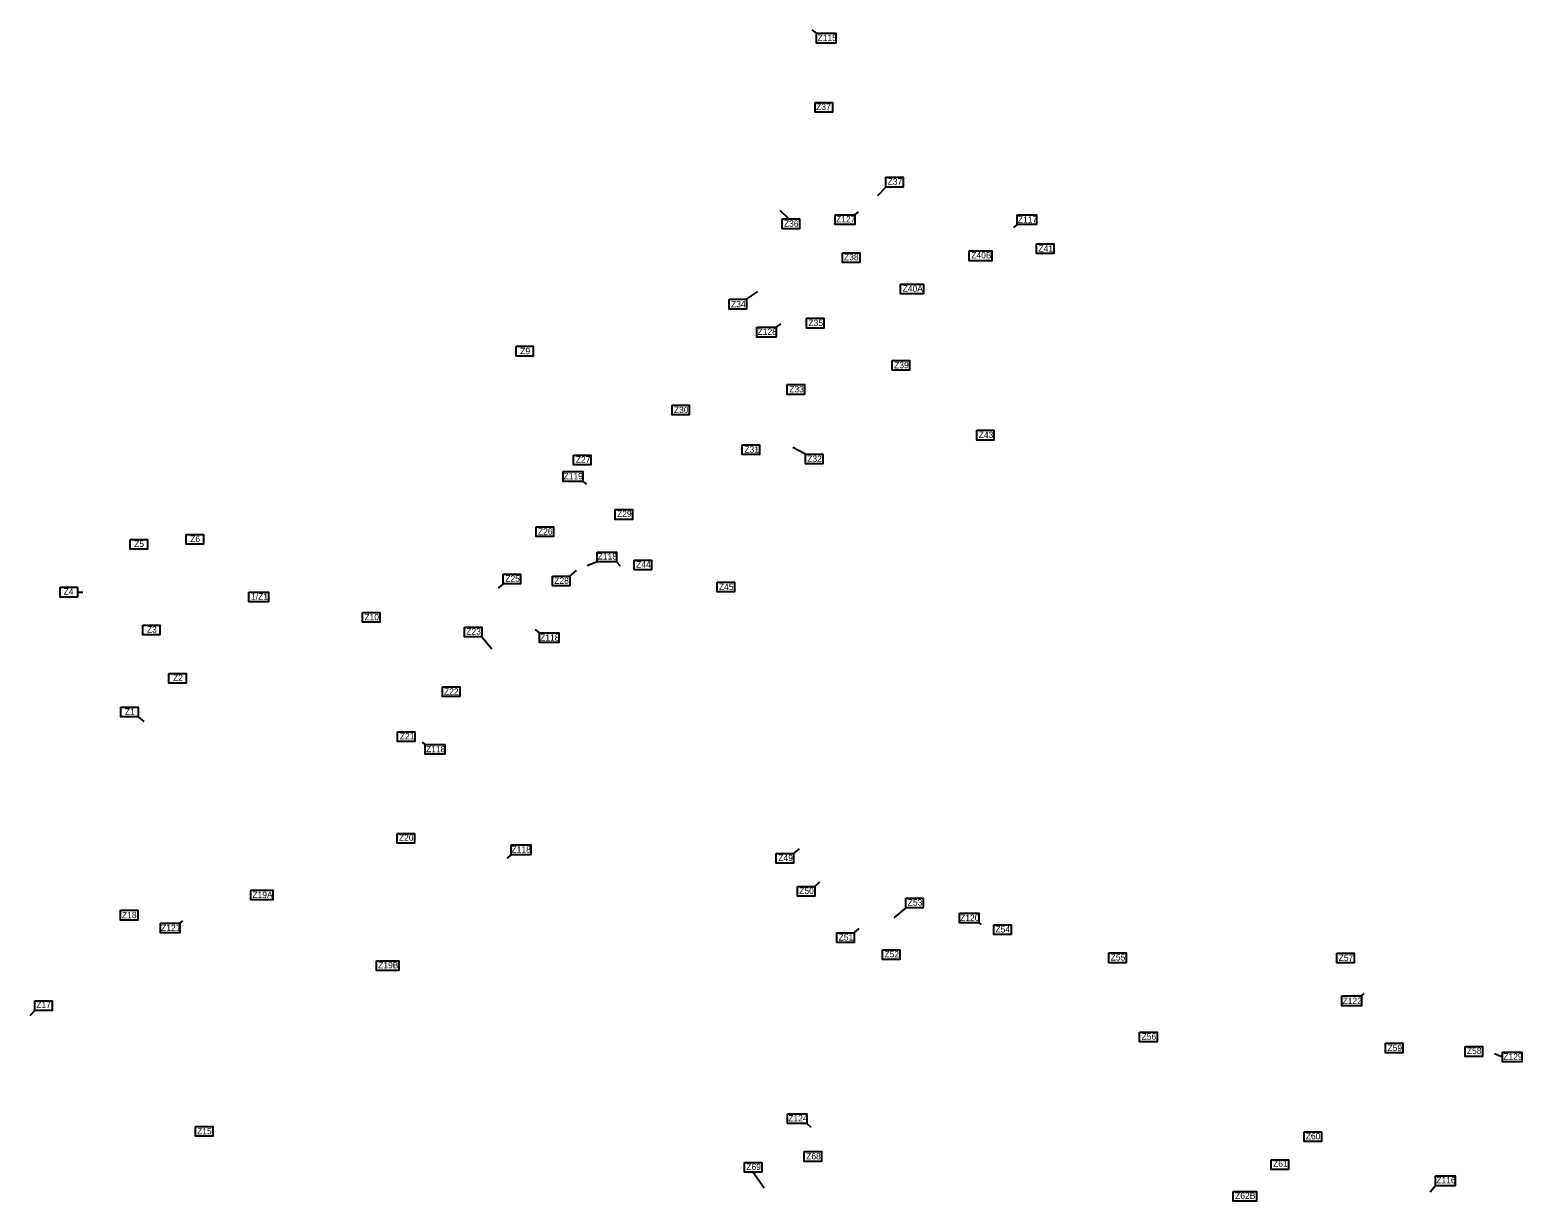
# Model space of a CAD drawing. Extents: x -443483 to -437761, y -1135258 to -1129797.
# Drawn here: x -443022 to -440666, y -1131646 to -1129797 of the extents above; entities that cross this region are included whole.
import ezdxf

# ---------------------------------------------------------------- set-up
doc = ezdxf.new("R2010")
doc.units = 0
doc.layers.add('Vrstva 3', color=7, linetype='Continuous')
doc.layers.add('Vrstva 8', color=7, linetype='Continuous')

msp = doc.modelspace()

# ---------------------------------------------------------------- linework, layer by layer
at = {"layer": 'Vrstva 3'}
for p, q in [((-441780.6, -1129802.1), (-441787.2, -1129796.7)), ((-441671, -1130044.8), (-441684, -1130058.8)), ((-441824.2, -1130095.2), (-441838, -1130081.7)), ((-441797.8, -1130466.6), (-441817.9, -1130456)), ((-442169.8, -1130659.1), (-442159.4, -1130650.4)), ((-442275.3, -1130671.3), (-442283.1, -1130678.3)), ((-442947.3, -1130684.5), (-442938.5, -1130684.6)), ((-442308.8, -1130754.9), (-442293.2, -1130773.8)), ((-442851.5, -1130881.4), (-442842.3, -1130888.4)), ((-441816.8, -1131096.9), (-441807.1, -1131089.6)), ((-441783.2, -1131148.9), (-441775.1, -1131141.9)), ((-441639.2, -1131182.7), (-441658.5, -1131198.7)), ((-441721, -1131222.3), (-441712.8, -1131215.4)), ((-443014.7, -1131344.8), (-443022.4, -1131353.5)), ((-441880.4, -1131600.1), (-441862.9, -1131625)), ((-440803, -1131621.5), (-440811.7, -1131631.9))]:
    msp.add_line(p, q, dxfattribs=at)
for points in [[(-441780.6, -1129802.1), (-441749.8, -1129802.1), (-441749.8, -1129817.5), (-441780.6, -1129817.5)], [(-441782.6, -1129911.3), (-441755.2, -1129911.3), (-441755.2, -1129926.7), (-441782.6, -1129926.7)], [(-441671, -1130029.4), (-441643.7, -1130029.4), (-441643.7, -1130044.8), (-441671, -1130044.8)], [(-441834.7, -1130095.2), (-441807.3, -1130095.2), (-441807.3, -1130110.6), (-441834.7, -1130110.6)], [(-441433.1, -1130134.4), (-441405.7, -1130134.4), (-441405.7, -1130149.8), (-441433.1, -1130149.8)], [(-441739.6, -1130148.5), (-441712.2, -1130148.5), (-441712.2, -1130163.9), (-441739.6, -1130163.9)], [(-441539.4, -1130145.7), (-441503.4, -1130145.7), (-441503.4, -1130161.1), (-441539.4, -1130161.1)], [(-441647.7, -1130198.3), (-441611.7, -1130198.3), (-441611.7, -1130213.7), (-441647.7, -1130213.7)], [(-441918.2, -1130222.1), (-441890.9, -1130222.1), (-441890.9, -1130237.5), (-441918.2, -1130237.5)], [(-441796.3, -1130252.1), (-441768.9, -1130252.1), (-441768.9, -1130267.5), (-441796.3, -1130267.5)], [(-442254.8, -1130296.3), (-442227.5, -1130296.3), (-442227.5, -1130311.7), (-442254.8, -1130311.7)], [(-441661.1, -1130318.6), (-441633.7, -1130318.6), (-441633.7, -1130334), (-441661.1, -1130334)], [(-441826.6, -1130356.8), (-441799.2, -1130356.8), (-441799.2, -1130372.2), (-441826.6, -1130372.2)], [(-442008.5, -1130389.3), (-441981.2, -1130389.3), (-441981.2, -1130404.7), (-442008.5, -1130404.7)], [(-441527.5, -1130428.9), (-441500.2, -1130428.9), (-441500.2, -1130444.3), (-441527.5, -1130444.3)], [(-441897.9, -1130451.8), (-441870.5, -1130451.8), (-441870.5, -1130467.2), (-441897.9, -1130467.2)], [(-442163.9, -1130468.1), (-442136.5, -1130468.1), (-442136.5, -1130483.5), (-442163.9, -1130483.5)], [(-441797.8, -1130466.6), (-441770.5, -1130466.6), (-441770.5, -1130482), (-441797.8, -1130482)], [(-442098.4, -1130554.1), (-442071.1, -1130554.1), (-442071.1, -1130569.5), (-442098.4, -1130569.5)], [(-442222.8, -1130581.2), (-442195.5, -1130581.2), (-442195.5, -1130596.5), (-442222.8, -1130596.5)], [(-442864.1, -1130601.3), (-442836.8, -1130601.3), (-442836.8, -1130616.7), (-442864.1, -1130616.7)], [(-442775.7, -1130593.4), (-442748.3, -1130593.4), (-442748.3, -1130608.8), (-442775.7, -1130608.8)], [(-442068.4, -1130633.9), (-442041.1, -1130633.9), (-442041.1, -1130649.3), (-442068.4, -1130649.3)], [(-442275.3, -1130655.9), (-442247.9, -1130655.9), (-442247.9, -1130671.3), (-442275.3, -1130671.3)], [(-442197.1, -1130659.1), (-442169.8, -1130659.1), (-442169.8, -1130674.5), (-442197.1, -1130674.5)], [(-441937.3, -1130668.5), (-441909.9, -1130668.5), (-441909.9, -1130683.9), (-441937.3, -1130683.9)], [(-442974.7, -1130676.8), (-442947.3, -1130676.8), (-442947.3, -1130692.2), (-442974.7, -1130692.2)], [(-442676.6, -1130684.2), (-442645.6, -1130684.2), (-442645.6, -1130699.6), (-442676.6, -1130699.6)], [(-442497.1, -1130716.5), (-442469.7, -1130716.5), (-442469.7, -1130731.9), (-442497.1, -1130731.9)], [(-442844.2, -1130736.3), (-442816.9, -1130736.3), (-442816.9, -1130751.7), (-442844.2, -1130751.7)], [(-442336.2, -1130739.6), (-442308.8, -1130739.6), (-442308.8, -1130754.9), (-442336.2, -1130754.9)], [(-442802.8, -1130812.7), (-442775.4, -1130812.7), (-442775.4, -1130828.1), (-442802.8, -1130828.1)], [(-442370.9, -1130833.9), (-442343.6, -1130833.9), (-442343.6, -1130849.2), (-442370.9, -1130849.2)], [(-442878.9, -1130866.1), (-442851.5, -1130866.1), (-442851.5, -1130881.4), (-442878.9, -1130881.4)], [(-442441.8, -1130904.7), (-442414.5, -1130904.7), (-442414.5, -1130920.1), (-442441.8, -1130920.1)], [(-442442.5, -1131065.5), (-442415.2, -1131065.5), (-442415.2, -1131080.9), (-442442.5, -1131080.9)], [(-441844.2, -1131096.9), (-441816.8, -1131096.9), (-441816.8, -1131112.3), (-441844.2, -1131112.3)], [(-442673.7, -1131154.7), (-442638.8, -1131154.7), (-442638.8, -1131170.1), (-442673.7, -1131170.1)], [(-441810.6, -1131148.9), (-441783.2, -1131148.9), (-441783.2, -1131164.3), (-441810.6, -1131164.3)], [(-441639.2, -1131167.3), (-441611.8, -1131167.3), (-441611.8, -1131182.7), (-441639.2, -1131182.7)], [(-442879.2, -1131186.7), (-442851.8, -1131186.7), (-442851.8, -1131202.1), (-442879.2, -1131202.1)], [(-441500.6, -1131209.7), (-441473.3, -1131209.7), (-441473.3, -1131225.1), (-441500.6, -1131225.1)], [(-441748.4, -1131222.3), (-441721, -1131222.3), (-441721, -1131237.7), (-441748.4, -1131237.7)], [(-441676, -1131249.1), (-441648.6, -1131249.1), (-441648.6, -1131264.5), (-441676, -1131264.5)], [(-441319, -1131254), (-441291.6, -1131254), (-441291.6, -1131269.4), (-441319, -1131269.4)], [(-440958.8, -1131254.3), (-440931.4, -1131254.3), (-440931.4, -1131269.7), (-440958.8, -1131269.7)], [(-442475.3, -1131266.3), (-442439.8, -1131266.3), (-442439.8, -1131281.7), (-442475.3, -1131281.7)], [(-443014.7, -1131329.4), (-442987.3, -1131329.4), (-442987.3, -1131344.8), (-443014.7, -1131344.8)], [(-441270.2, -1131379), (-441242.8, -1131379), (-441242.8, -1131394.4), (-441270.2, -1131394.4)], [(-440882, -1131396.5), (-440854.6, -1131396.5), (-440854.6, -1131411.9), (-440882, -1131411.9)], [(-440756.3, -1131401.9), (-440728.9, -1131401.9), (-440728.9, -1131417.3), (-440756.3, -1131417.3)], [(-442760.6, -1131528), (-442733.3, -1131528), (-442733.3, -1131543.4), (-442760.6, -1131543.4)], [(-441010.2, -1131536.4), (-440982.9, -1131536.4), (-440982.9, -1131551.8), (-441010.2, -1131551.8)], [(-441799.8, -1131567.7), (-441772.4, -1131567.7), (-441772.4, -1131583.1), (-441799.8, -1131583.1)], [(-441894.2, -1131584.7), (-441866.9, -1131584.7), (-441866.9, -1131600.1), (-441894.2, -1131600.1)], [(-441062.3, -1131580.5), (-441035, -1131580.5), (-441035, -1131595.9), (-441062.3, -1131595.9)], [(-440803, -1131606.1), (-440772.3, -1131606.1), (-440772.3, -1131621.5), (-440803, -1131621.5)], [(-441122.8, -1131630.5), (-441085.9, -1131630.5), (-441085.9, -1131645.9), (-441122.8, -1131645.9)]]:
    msp.add_lwpolyline(points, close=True, dxfattribs=at)
at = {"layer": 'Vrstva 8'}
for p, q in [((-441720.1, -1130088.6), (-441714.3, -1130084)), ((-441463.6, -1130104.2), (-441469.4, -1130108.5)), ((-441890.9, -1130222.1), (-441873, -1130210)), ((-441844, -1130266.2), (-441836.1, -1130260.9)), ((-442149.3, -1130509.6), (-442143.6, -1130514.2)), ((-442126.7, -1130636.5), (-442142.2, -1130643.1)), ((-442095.9, -1130636.5), (-442090.5, -1130642.7)), ((-442217.8, -1130748.4), (-442224.2, -1130743.6)), ((-442398, -1130924.7), (-442402.3, -1130921.1)), ((-442262.3, -1131099), (-442269.2, -1131104.3)), ((-442785.3, -1131206.9), (-442780.8, -1131203.4)), ((-441523.9, -1131206.4), (-441520.2, -1131209.2)), ((-440920.2, -1131322), (-440915.5, -1131317.9)), ((-440697.5, -1131418.4), (-440709.9, -1131413.3)), ((-441795.5, -1131523.2), (-441789.2, -1131529))]:
    msp.add_line(p, q, dxfattribs=at)
for points in [[(-441750.9, -1130088.6), (-441720.1, -1130088.6), (-441720.1, -1130104), (-441750.9, -1130104)], [(-441463.6, -1130088.8), (-441432.8, -1130088.8), (-441432.8, -1130104.2), (-441463.6, -1130104.2)], [(-441463.6, -1130088.8), (-441432.8, -1130088.8), (-441432.8, -1130104.2), (-441463.6, -1130104.2)], [(-441874.8, -1130266.2), (-441844, -1130266.2), (-441844, -1130281.6), (-441874.8, -1130281.6)], [(-442180.1, -1130494.2), (-442149.3, -1130494.2), (-442149.3, -1130509.6), (-442180.1, -1130509.6)], [(-442126.7, -1130621.1), (-442095.9, -1130621.1), (-442095.9, -1130636.5), (-442126.7, -1130636.5)], [(-442217.8, -1130748.4), (-442187, -1130748.4), (-442187, -1130763.8), (-442217.8, -1130763.8)], [(-442398, -1130924.7), (-442367.2, -1130924.7), (-442367.2, -1130940.1), (-442398, -1130940.1)], [(-442262.3, -1131083.6), (-442231.5, -1131083.6), (-442231.5, -1131099), (-442262.3, -1131099)], [(-441554.7, -1131191), (-441523.9, -1131191), (-441523.9, -1131206.4), (-441554.7, -1131206.4)], [(-442816.1, -1131206.9), (-442785.3, -1131206.9), (-442785.3, -1131222.3), (-442816.1, -1131222.3)], [(-440951, -1131322), (-440920.2, -1131322), (-440920.2, -1131337.4), (-440951, -1131337.4)], [(-440697.5, -1131410.7), (-440666.8, -1131410.7), (-440666.8, -1131426.1), (-440697.5, -1131426.1)], [(-441826.3, -1131507.9), (-441795.5, -1131507.9), (-441795.5, -1131523.2), (-441826.3, -1131523.2)]]:
    msp.add_lwpolyline(points, close=True, dxfattribs=at)

# ---------------------------------------------------------------- texts
at = {"layer": 'Vrstva 3'}
for s, p in [('Z115', (-441778.7, -1129814.2)), ('Z37', (-441780.9, -1129923.3)), ('Z37', (-441668.1, -1130041.2)), ('Z36', (-441831.8, -1130107.5)), ('Z38', (-441736.9, -1130160.4)), ('Z40B', (-441536, -1130157.5)), ('Z41', (-441430, -1130146.8)), ('Z40A', (-441644.4, -1130210.1)), ('Z34', (-441915.3, -1130234.7)), ('Z35', (-441793.1, -1130264.3)), ('Z9', (-442248.2, -1130308.7)), ('Z39', (-441657.8, -1130330.9)), ('Z33', (-441823.4, -1130369)), ('Z30', (-442005.5, -1130401.6)), ('Z43', (-441524.3, -1130441.2)), ('Z31', (-441894.2, -1130464.1)), ('Z27', (-442160.4, -1130480.1)), ('Z32', (-441795, -1130478.8)), ('Z29', (-442095.2, -1130565.8)), ('Z5', (-442857.7, -1130613.2)), ('Z6', (-442769.2, -1130605.4)), ('Z26', (-442220.1, -1130593.6)), ('Z44', (-442065.1, -1130645.7)), ('Z25', (-442271.7, -1130668)), ('Z28', (-442194.4, -1130671.3)), ('Z45', (-441934.4, -1130681)), ('Z4', (-442969.1, -1130688.5)), ('1/Z1', (-442673.1, -1130696.4)), ('Z10', (-442494.1, -1130728.9)), ('Z3', (-442837.5, -1130748.5)), ('Z23', (-442333.3, -1130751.4)), ('Z2', (-442796.3, -1130824.6)), ('Z22', (-442368.4, -1130846.3)), ('Z1', (-442872.3, -1130878.1)), ('Z21', (-442438.2, -1130916.8)), ('Z20', (-442439.7, -1131077)), ('Z49', (-441840.7, -1131108.8)), ('Z19A', (-442671, -1131167.2)), ('Z50', (-441807.7, -1131160.9)), ('Z53', (-441636.3, -1131179.3)), ('Z18', (-442876.9, -1131199.2)), ('Z54', (-441497.9, -1131221.7)), ('Z51', (-441745.4, -1131234.4)), ('Z52', (-441673.1, -1131261.1)), ('Z55', (-441315.9, -1131266)), ('Z57', (-440956, -1131266.7)), ('Z19B', (-442472.4, -1131278.3)), ('Z17', (-443012.2, -1131341)), ('Z56', (-441267.1, -1131391.1)), ('Z59', (-440878.9, -1131409)), ('Z58', (-440753.5, -1131413.6)), ('Z15', (-442758.3, -1131540.5)), ('Z60', (-441007.9, -1131548.3)), ('Z68', (-441796.7, -1131580)), ('Z69', (-441891.2, -1131596.7)), ('Z61', (-441059.6, -1131591.7)), ('Z116', (-440801.8, -1131617.8)), ('Z62B', (-441119.4, -1131642.3))]:
    msp.add_text(s, height=10, dxfattribs=at).set_placement(p)
at = {"layer": 'Vrstva 8'}
for s, p in [('Z127', (-441749.5, -1130100.6)), ('Z117', (-441462.5, -1130101.2)), ('Z128', (-441873.4, -1130278.2)), ('Z119', (-442179.6, -1130506.2)), ('Z118', (-442125.9, -1130632.9)), ('Z118', (-442216.7, -1130760.9)), ('Z118', (-442396.9, -1130937.1)), ('Z118', (-442261.9, -1131095.6)), ('Z120', (-441553.6, -1131203.5)), ('Z121', (-442815.1, -1131219.3)), ('Z122', (-440949.9, -1131334.5)), ('Z129', (-440696.1, -1131422.7)), ('Z124', (-441824.9, -1131520.1))]:
    msp.add_text(s, height=10, dxfattribs=at).set_placement(p)

doc.saveas('drawing.dxf')
